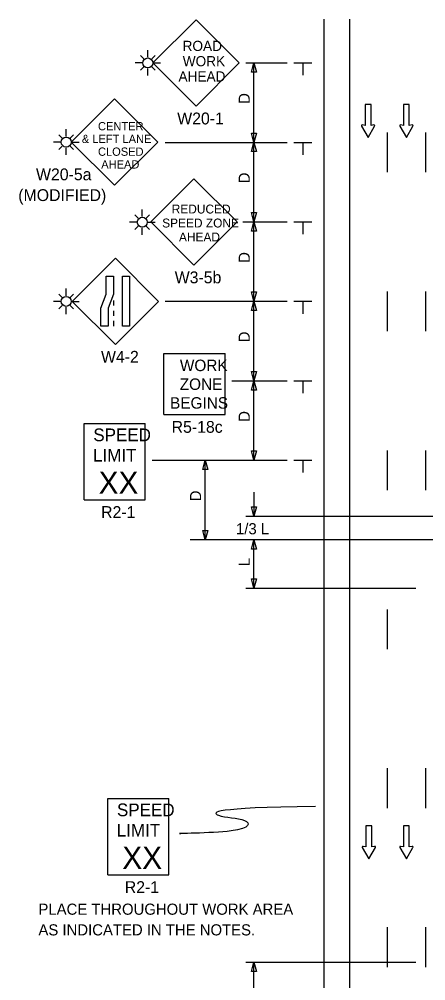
# Model space of a CAD drawing. Extents: x 16038 to 19504, y 5710 to 8321.
# Drawn here: x 16747 to 17003, y 6320 to 6925 of the extents above; entities that cross this region are included whole.
import ezdxf

# ---------------------------------------------------------------- set-up
doc = ezdxf.new("R2010")
doc.units = 0
for name, color, linetype in [('ALI_LEGAL_EX', 7, 'Continuous'), ('MT_SCRATCH_LEVEL_E', 7, 'Continuous'), ('PAVT_EDGE_EX', 7, 'Continuous'), ('TRAFFIC_SIGNS_PR', 7, 'Continuous'), ('TYPICAL_EX', 7, 'Continuous'), ('TYPICAL_TEXT_DIMEN_PR', 7, 'Continuous')]:
    doc.layers.add(name, color=color, linetype=linetype)

msp = doc.modelspace()

# ---------------------------------------------------------------- linework, layer by layer
at = {"layer": 'ALI_LEGAL_EX'}
for points in [[(16978.71, 6829.12), (16978.71, 6854.12)], [(17002.71, 6829.12), (17002.71, 6854.12)], [(16978.71, 6729.12), (16978.71, 6754.12)], [(17002.71, 6729.12), (17002.71, 6754.12)], [(16978.71, 6629.12), (16978.71, 6654.12)], [(17002.71, 6629.12), (17002.71, 6654.12)], [(16978.71, 6529.12), (16978.71, 6554.12)], [(16978.71, 6429.12), (16978.71, 6454.12)], [(17002.71, 6429.12), (17002.71, 6454.12)], [(16978.71, 6329.12), (16978.71, 6354.12)], [(17002.71, 6329.12), (17002.71, 6354.12)]]:
    msp.add_lwpolyline(points, dxfattribs=at)
at = {"layer": 'MT_SCRATCH_LEVEL_E'}
for p, q in [((16968.31, 6871.76), (16964.57, 6871.76)), ((16964.57, 6871.76), (16964.57, 6858.5)), ((16968.31, 6871.76), (16964.57, 6871.76)), ((16964.57, 6871.76), (16964.57, 6858.5)), ((16968.31, 6858.5), (16968.31, 6871.76)), ((16968.31, 6858.5), (16968.31, 6871.76)), ((16992.38, 6871.76), (16988.64, 6871.76)), ((16988.64, 6871.76), (16988.64, 6858.5)), ((16992.38, 6871.76), (16988.64, 6871.76)), ((16988.64, 6871.76), (16988.64, 6858.5)), ((16992.38, 6858.5), (16992.38, 6871.76)), ((16992.38, 6858.5), (16992.38, 6871.76)), ((16962.31, 6858.13), (16966.46, 6850.89)), ((16962.31, 6858.13), (16966.46, 6850.89)), ((16964.57, 6858.5), (16962.79, 6858.82)), ((16964.57, 6858.5), (16962.79, 6858.82)), ((16966.46, 6850.89), (16970.57, 6858.13)), ((16966.46, 6850.89), (16970.57, 6858.13)), ((16970.08, 6858.82), (16968.31, 6858.5)), ((16970.08, 6858.82), (16968.31, 6858.5)), ((16986.38, 6858.13), (16990.53, 6850.89)), ((16986.38, 6858.13), (16990.53, 6850.89)), ((16988.64, 6858.5), (16986.86, 6858.82)), ((16988.64, 6858.5), (16986.86, 6858.82)), ((16990.53, 6850.89), (16994.64, 6858.13)), ((16990.53, 6850.89), (16994.64, 6858.13)), ((16994.16, 6858.82), (16992.38, 6858.5)), ((16994.16, 6858.82), (16992.38, 6858.5)), ((16968.81, 6417.97), (16965.07, 6417.97)), ((16965.07, 6417.97), (16965.07, 6404.71)), ((16968.81, 6417.97), (16965.07, 6417.97)), ((16965.07, 6417.97), (16965.07, 6404.71)), ((16968.81, 6404.71), (16968.81, 6417.97)), ((16968.81, 6404.71), (16968.81, 6417.97)), ((16992.38, 6417.97), (16988.64, 6417.97)), ((16988.64, 6417.97), (16988.64, 6404.71)), ((16992.38, 6417.97), (16988.64, 6417.97)), ((16988.64, 6417.97), (16988.64, 6404.71)), ((16992.38, 6404.71), (16992.38, 6417.97)), ((16992.38, 6404.71), (16992.38, 6417.97)), ((16962.81, 6404.34), (16966.96, 6397.1)), ((16962.81, 6404.34), (16966.96, 6397.1)), ((16965.07, 6404.71), (16963.29, 6405.03)), ((16965.07, 6404.71), (16963.29, 6405.03)), ((16966.96, 6397.1), (16971.07, 6404.34)), ((16966.96, 6397.1), (16971.07, 6404.34)), ((16970.59, 6405.03), (16968.81, 6404.71)), ((16970.59, 6405.03), (16968.81, 6404.71)), ((16986.38, 6404.34), (16990.53, 6397.1)), ((16986.38, 6404.34), (16990.53, 6397.1)), ((16988.64, 6404.71), (16986.86, 6405.03)), ((16988.64, 6404.71), (16986.86, 6405.03)), ((16990.53, 6397.1), (16994.64, 6404.34)), ((16990.53, 6397.1), (16994.64, 6404.34)), ((16994.16, 6405.03), (16992.38, 6404.71)), ((16994.16, 6405.03), (16992.38, 6404.71))]:
    msp.add_line(p, q, dxfattribs=at)
for centre, start, end in [((16962.72, 6858.36), 80.03619, 209.77312), ((16962.72, 6858.36), 80.03619, 209.77312), ((16970.16, 6858.36), 330.42484, 99.96381), ((16970.16, 6858.36), 330.42484, 99.96381), ((16986.79, 6858.36), 80.03619, 209.77312), ((16986.79, 6858.36), 80.03619, 209.77312), ((16994.23, 6858.36), 330.42484, 99.96381), ((16994.23, 6858.36), 330.42484, 99.96381), ((16963.22, 6404.57), 80.03619, 209.77312), ((16963.22, 6404.57), 80.03619, 209.77312), ((16970.66, 6404.57), 330.42484, 99.96381), ((16970.66, 6404.57), 330.42484, 99.96381), ((16986.79, 6404.57), 80.03619, 209.77312), ((16986.79, 6404.57), 80.03619, 209.77312), ((16994.23, 6404.57), 330.42484, 99.96381), ((16994.23, 6404.57), 330.42484, 99.96381)]:
    msp.add_arc(centre, 0.463, start, end, dxfattribs=at)
at = {"layer": 'PAVT_EDGE_EX'}
for p, q in [((16954.71, 6925.32), (16954.71, 6077.44)), ((16938.71, 6780.67), (16938.71, 6077.44))]:
    msp.add_line(p, q, dxfattribs=at)
at = {"layer": 'TRAFFIC_SIGNS_PR'}
for p, q in [((16858.27, 6924.99), (16831.09, 6897.81)), ((16885.46, 6897.81), (16858.27, 6924.99)), ((16825.42, 6900.32), (16823.31, 6902.43)), ((16827.93, 6901.36), (16827.93, 6905.86)), ((16830.45, 6900.32), (16832.56, 6902.43)), ((16824.78, 6897.81), (16819.94, 6897.81)), ((16831.09, 6897.81), (16835.97, 6897.81)), ((16831.09, 6897.81), (16858.27, 6870.62)), ((16858.27, 6870.62), (16885.46, 6897.81)), ((16825.42, 6895.29), (16823.31, 6893.19)), ((16827.93, 6889.84), (16827.93, 6894.25)), ((16830.45, 6895.29), (16832.55, 6893.19)), ((16807.01, 6875.22), (16779.82, 6848.03)), ((16834.2, 6848.03), (16807.01, 6875.22)), ((16776.67, 6851.58), (16776.67, 6856.09)), ((16773.51, 6848.03), (16768.68, 6848.03)), ((16774.16, 6850.54), (16772.05, 6852.65)), ((16779.18, 6850.54), (16781.29, 6852.65)), ((16779.82, 6848.03), (16784.7, 6848.03)), ((16779.82, 6848.03), (16807.01, 6820.84)), ((16807.01, 6820.84), (16834.2, 6848.03)), ((16774.15, 6845.52), (16772.05, 6843.41)), ((16776.67, 6840.06), (16776.67, 6844.48)), ((16779.18, 6845.52), (16781.29, 6843.41)), ((16856.92, 6824.98), (16829.76, 6797.82)), ((16884.07, 6797.82), (16856.92, 6824.98)), ((16824.49, 6801.19), (16824.49, 6805.69)), ((16821.98, 6800.15), (16819.87, 6802.25)), ((16827, 6800.15), (16829.11, 6802.25)), ((16821.34, 6797.63), (16816.5, 6797.63)), ((16821.98, 6795.12), (16819.87, 6793.01)), ((16824.49, 6789.67), (16824.49, 6794.08)), ((16827, 6795.12), (16829.11, 6793.01)), ((16827.64, 6797.63), (16832.53, 6797.63)), ((16829.76, 6797.82), (16856.92, 6770.67)), ((16856.92, 6770.67), (16884.07, 6797.82)), ((16807.56, 6775.01), (16780.4, 6747.86)), ((16834.71, 6747.86), (16807.56, 6775.01)), ((16774.15, 6750.37), (16772.05, 6752.48)), ((16776.67, 6751.41), (16776.67, 6755.91)), ((16779.18, 6750.37), (16781.29, 6752.48)), ((16773.51, 6747.86), (16768.68, 6747.86)), ((16774.15, 6745.35), (16772.05, 6743.24)), ((16776.67, 6739.89), (16776.67, 6744.3)), ((16779.18, 6745.35), (16781.29, 6743.24)), ((16779.82, 6747.86), (16784.7, 6747.86)), ((16780.4, 6747.86), (16807.56, 6720.71)), ((16806.31, 6748.35), (16806.31, 6745.15)), ((16807.56, 6720.71), (16834.71, 6747.86)), ((16806.31, 6741.95), (16806.31, 6738.75)), ((16806.31, 6735.55), (16806.31, 6732.35)), ((16838.12, 6676.6), (16838.12, 6715)), ((16838.12, 6715), (16876.52, 6715)), ((16876.52, 6676.6), (16876.52, 6715)), ((16838.12, 6676.6), (16876.52, 6676.6)), ((16787.89, 6671.02), (16826.29, 6671.02)), ((16787.89, 6623.02), (16787.89, 6671.02)), ((16826.29, 6623.02), (16826.29, 6671.02)), ((16787.89, 6623.02), (16826.29, 6623.02)), ((16802.79, 6435.11), (16841.19, 6435.11)), ((16802.79, 6387.11), (16802.79, 6435.11)), ((16841.19, 6387.11), (16841.19, 6435.11)), ((16802.79, 6387.11), (16841.19, 6387.11))]:
    msp.add_line(p, q, dxfattribs=at)
for points in [[(16806.31, 6763.6), (16806.31, 6752.41), (16802.97, 6743.53), (16802.97, 6732.35), (16798.47, 6732.35), (16798.47, 6743.53), (16801.82, 6752.41), (16801.82, 6763.6)], [(16816.45, 6763.6), (16816.45, 6732.35), (16811.95, 6732.35), (16811.95, 6763.6)]]:
    msp.add_lwpolyline(points, close=True, dxfattribs=at)
for centre in [(16827.93, 6897.81), (16776.67, 6848.03), (16824.49, 6797.63), (16776.67, 6747.86)]:
    msp.add_circle(centre, 3.15, dxfattribs=at)
at = {"layer": 'TYPICAL_EX'}
msp.add_line((16938.71, 6925.32), (16938.71, 6077.44), dxfattribs=at)
at = {"layer": 'TYPICAL_TEXT_DIMEN_PR'}
for p, q in [((16889.61, 6897.88), (16915.61, 6897.88)), ((16893.04, 6892.02), (16894.61, 6897.88)), ((16894.61, 6847.88), (16894.61, 6897.88)), ((16894.61, 6897.88), (16896.18, 6892.02)), ((16919.86, 6897.88), (16931.11, 6897.88)), ((16925.49, 6897.88), (16925.49, 6890.1)), ((16894.61, 6892.02), (16893.04, 6892.02)), ((16896.18, 6892.02), (16894.61, 6892.02)), ((16894.61, 6847.88), (16893.04, 6853.74)), ((16893.04, 6853.74), (16894.61, 6853.74)), ((16894.61, 6853.74), (16896.18, 6853.74)), ((16896.18, 6853.74), (16894.61, 6847.88)), ((16838.81, 6847.88), (16915.61, 6847.88)), ((16889.61, 6847.88), (16915.61, 6847.88)), ((16893.04, 6842.02), (16894.61, 6847.88)), ((16894.61, 6797.88), (16894.61, 6847.88)), ((16894.61, 6847.88), (16896.18, 6842.02)), ((16919.86, 6847.88), (16931.11, 6847.88)), ((16925.49, 6847.88), (16925.49, 6840.1)), ((16894.61, 6842.02), (16893.04, 6842.02)), ((16896.18, 6842.02), (16894.61, 6842.02)), ((16894.61, 6797.88), (16893.04, 6803.74)), ((16893.04, 6803.74), (16894.61, 6803.74)), ((16894.61, 6803.74), (16896.18, 6803.74)), ((16896.18, 6803.74), (16894.61, 6797.88)), ((16887.66, 6797.88), (16915.61, 6797.88)), ((16889.61, 6797.88), (16915.61, 6797.88)), ((16893.04, 6792.02), (16894.61, 6797.88)), ((16894.61, 6797.88), (16896.18, 6792.02)), ((16894.61, 6747.88), (16894.61, 6797.88)), ((16919.86, 6797.88), (16931.11, 6797.88)), ((16925.49, 6797.88), (16925.49, 6790.1)), ((16894.61, 6792.02), (16893.04, 6792.02)), ((16896.18, 6792.02), (16894.61, 6792.02)), ((16894.61, 6747.88), (16893.04, 6753.74)), ((16893.04, 6753.74), (16894.61, 6753.74)), ((16894.61, 6753.74), (16896.18, 6753.74)), ((16896.18, 6753.74), (16894.61, 6747.88)), ((16838.81, 6747.88), (16915.61, 6747.88)), ((16893.04, 6742.02), (16894.61, 6747.88)), ((16894.61, 6747.88), (16896.18, 6742.02)), ((16894.61, 6697.88), (16894.61, 6747.88)), ((16919.86, 6747.88), (16931.11, 6747.88)), ((16925.49, 6747.88), (16925.49, 6740.1)), ((16894.61, 6742.02), (16893.04, 6742.02)), ((16896.18, 6742.02), (16894.61, 6742.02)), ((16894.61, 6697.88), (16893.04, 6703.74)), ((16893.04, 6703.74), (16894.61, 6703.74)), ((16894.61, 6703.74), (16896.18, 6703.74)), ((16896.18, 6703.74), (16894.61, 6697.88)), ((16880.83, 6697.88), (16915.61, 6697.88)), ((16893.04, 6692.02), (16894.61, 6697.88)), ((16894.61, 6647.88), (16894.61, 6697.88)), ((16894.61, 6697.88), (16896.18, 6692.02)), ((16919.86, 6697.88), (16931.11, 6697.88)), ((16925.49, 6697.88), (16925.49, 6690.1)), ((16894.61, 6692.02), (16893.04, 6692.02)), ((16896.18, 6692.02), (16894.61, 6692.02)), ((16894.61, 6647.88), (16893.04, 6653.74)), ((16893.04, 6653.74), (16894.61, 6653.74)), ((16894.61, 6653.74), (16896.18, 6653.74)), ((16896.18, 6653.74), (16894.61, 6647.88)), ((16830.75, 6647.88), (16915.61, 6647.88)), ((16862.46, 6642.02), (16864.03, 6647.88)), ((16864.03, 6647.88), (16865.6, 6642.02)), ((16864.03, 6597.88), (16864.03, 6647.88)), ((16919.86, 6647.88), (16931.11, 6647.88)), ((16925.49, 6647.88), (16925.49, 6640.1)), ((16864.03, 6642.02), (16862.46, 6642.02)), ((16865.6, 6642.02), (16864.03, 6642.02)), ((16894.61, 6627.73), (16894.61, 6612.8)), ((16894.61, 6612.8), (16893.04, 6618.67)), ((16893.04, 6618.67), (16894.61, 6618.67)), ((16894.61, 6618.67), (16896.18, 6618.67)), ((16896.18, 6618.67), (16894.61, 6612.8)), ((16889.61, 6612.8), (17039.81, 6612.8)), ((16864.03, 6597.88), (16862.46, 6603.74)), ((16862.46, 6603.74), (16864.03, 6603.74)), ((16864.03, 6603.74), (16865.6, 6603.74)), ((16865.6, 6603.74), (16864.03, 6597.88)), ((17018.36, 6597.88), (16854.51, 6597.88)), ((16893.04, 6592.02), (16894.61, 6597.88)), ((16894.61, 6567.35), (16894.61, 6597.88)), ((16894.61, 6597.88), (16896.18, 6592.02)), ((16894.61, 6592.02), (16893.04, 6592.02)), ((16896.18, 6592.02), (16894.61, 6592.02)), ((16894.61, 6567.35), (16893.04, 6573.21)), ((16893.04, 6573.21), (16894.61, 6573.21)), ((16894.61, 6573.21), (16896.18, 6573.21)), ((16896.18, 6573.21), (16894.61, 6567.35)), ((16889.61, 6567.35), (16996.54, 6567.35)), ((16889.61, 6332.13), (16996.39, 6332.13)), ((16893.04, 6326.27), (16894.61, 6332.13)), ((16894.61, 6273.48), (16894.61, 6332.13)), ((16894.61, 6332.13), (16896.18, 6326.27)), ((16894.61, 6326.27), (16893.04, 6326.27)), ((16896.18, 6326.27), (16894.61, 6326.27))]:
    msp.add_line(p, q, dxfattribs=at)
msp.add_open_spline([(16933.36, 6430.12), (16867.61, 6429.41), (16868.58, 6423.01), (16892.73, 6423.01), (16892.73, 6413.1), (16843.08, 6413.1), (16848.61, 6413.1)], degree=3, dxfattribs=at)

# ---------------------------------------------------------------- texts
at = {"layer": 'TRAFFIC_SIGNS_PR'}
for s, height, p in [('ROAD', 6.408, (16849.81, 6905.35)), ('WORK', 6.408, (16849.91, 6895.74)), ('AHEAD', 6.408, (16847.22, 6886.13)), ('W20-1', 7.449, (16846.43, 6859.17)), ('CENTER', 5.206, (16796.63, 6855.44)), ('& LEFT LANE', 5.2065, (16786.49, 6847.43)), ('CLOSED', 5.206, (16796.63, 6839.42)), ('AHEAD', 5.206, (16798.66, 6831.41)), ('W20-5a', 7.449, (16757.65, 6824.02)), ('(MODIFIED)', 7.449, (16746.49, 6810.96)), ('REDUCED', 5.6, (16842.97, 6803.13)), ('SPEED ZONE', 5.6, (16836.97, 6794.33)), ('AHEAD', 5.6, (16847.53, 6785.53)), ('W3-5b', 7.44, (16844.87, 6759.23)), ('W4-2', 7.44, (16798.52, 6709.27)), ('WORK', 7.217, (16848.12, 6703.97)), ('ZONE', 7.217, (16848, 6692.15)), ('BEGINS', 7.217, (16841.93, 6680.35)), ('R5-18c', 7.44, (16842.93, 6665.16)), ('SPEED', 8, (16793.66, 6659.88)), ('LIMIT', 8, (16793.49, 6647.08)), ('XX', 14.031, (16797, 6626.78)), ('R2-1', 7.44, (16798.57, 6611.58)), ('SPEED', 8, (16808.55, 6423.98)), ('LIMIT', 8, (16808.39, 6411.18)), ('XX', 14.031, (16811.9, 6390.87)), ('R2-1', 7.44, (16813.46, 6375.67)), ('PLACE THROUGHOUT WORK AREA', 7, (16759.18, 6362)), ('AS INDICATED IN THE NOTES.', 7, (16759.18, 6349))]:
    msp.add_text(s, height=height, dxfattribs=at).set_placement(p)
at = {"layer": 'TYPICAL_TEXT_DIMEN_PR'}
for s, p in [('D', (16892.05, 6872.1)), ('D', (16892.05, 6822.1)), ('D', (16892.05, 6772.1)), ('D', (16892.05, 6722.1)), ('D', (16892.05, 6672.1)), ('D', (16861.47, 6622.1)), ('L', (16892.05, 6581.21))]:
    msp.add_text(s, height=7, rotation=90, dxfattribs=at).set_placement(p)
msp.add_text('1/3 L', height=7, dxfattribs=at).set_placement((16883.4, 6601.33))

doc.saveas('drawing.dxf')
